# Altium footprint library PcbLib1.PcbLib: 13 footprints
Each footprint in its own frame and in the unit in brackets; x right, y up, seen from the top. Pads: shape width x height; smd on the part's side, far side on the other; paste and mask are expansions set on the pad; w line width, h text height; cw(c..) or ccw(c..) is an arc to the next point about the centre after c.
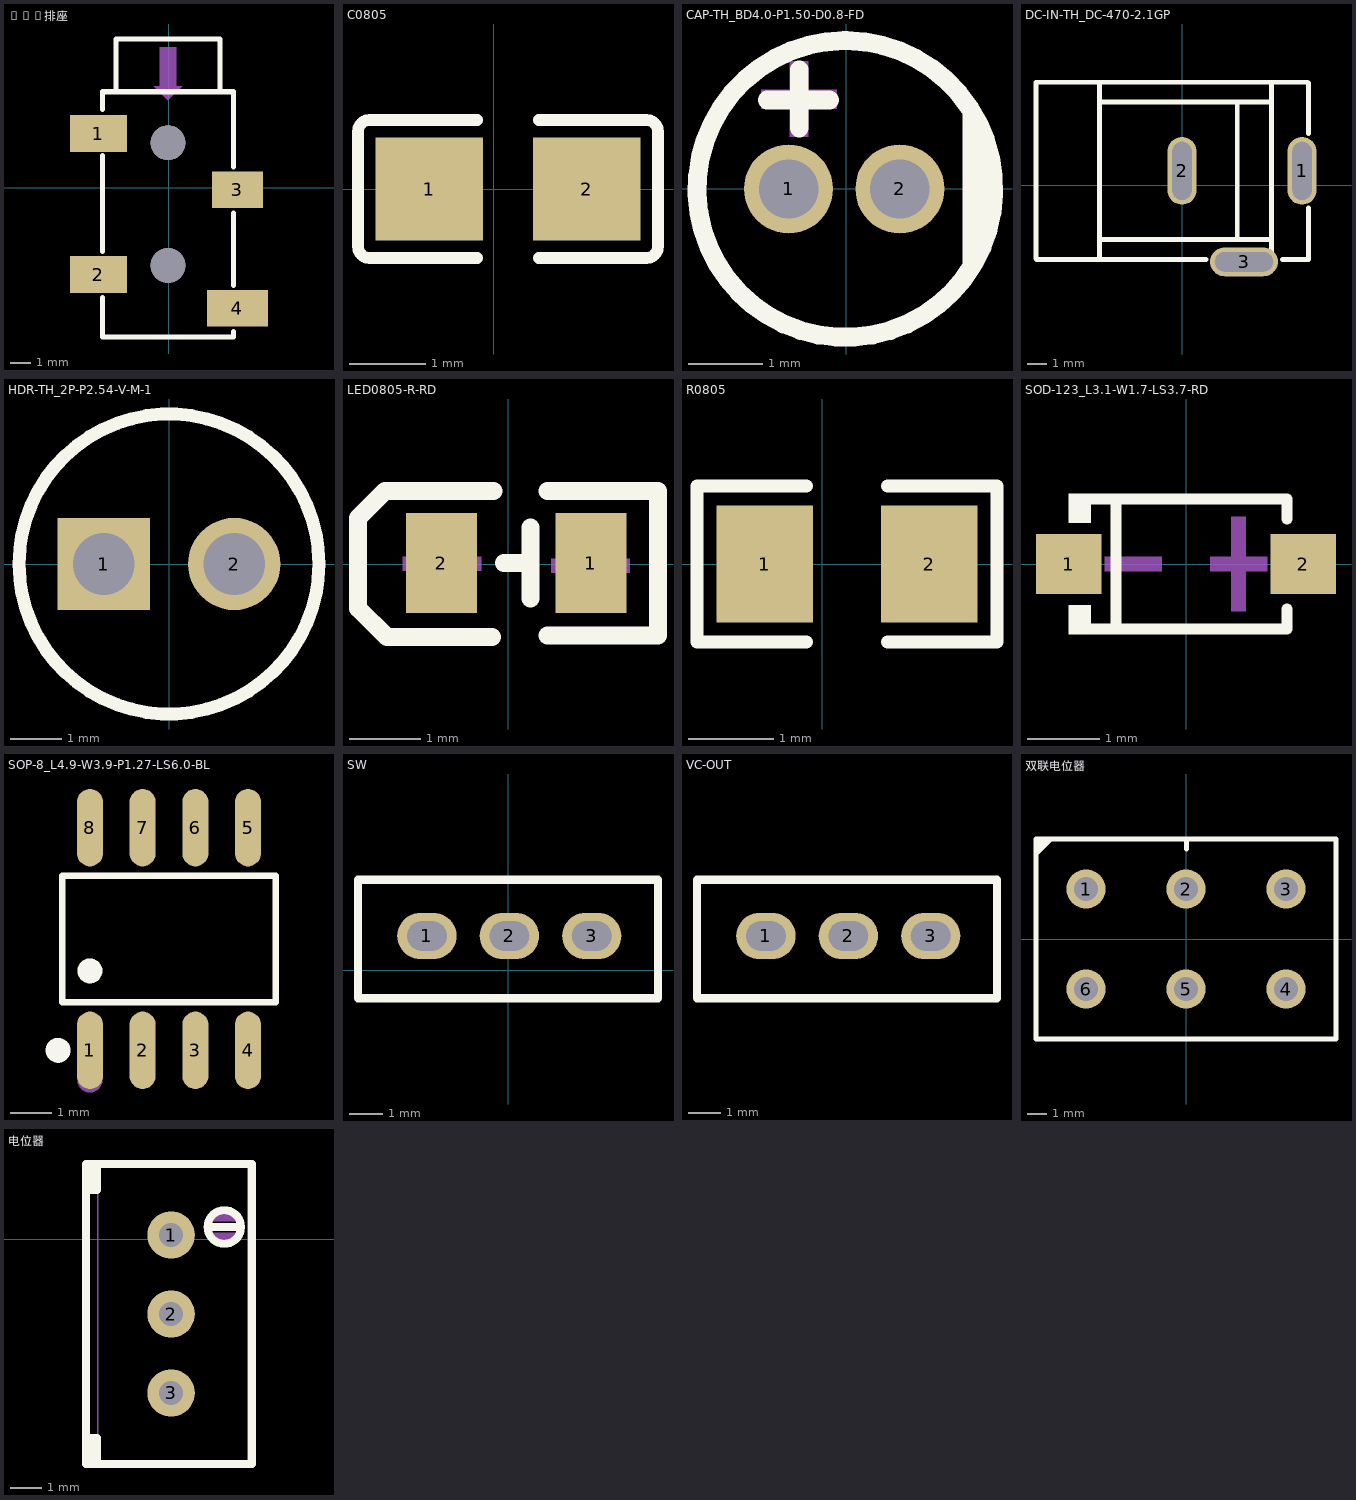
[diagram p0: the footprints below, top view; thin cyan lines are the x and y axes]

## 3.5排座 [mm]
pads (6):
  rect 2.8x1.8 smd: 1(-3.45,2.66) 2(-3.45,-4.24)
  rect 2.5x1.8 smd: 3(3.35,-0.09)
  rect 3x1.8 smd: 4(3.35,-5.89)
  round 1.7 hole 1.7 unplated: ""(-0.05,-3.79) ""(-0.05,2.21)
Top Overlay:
  lines w0.254: -3.25,-5.371 -3.25,-7.29 3.15,-7.29 3.15,-7.021 ; -3.25,-3.109 -3.25,-2.959 -3.25,1.579 ; -3.25,3.841 -3.25,4.71 3.15,4.71 3.15,1.041 ; -2.59,4.71 -2.59,6.742 -2.59,7.29 2.49,7.29 2.49,6.598 ; 2.49,4.71 2.49,6.742 ; 3.15,-4.759 3.15,-1.221
Mechanical 15:
  region: -0.45,6.885 -0.45,4.985 -0.75,4.985 -0.05,4.285 0.65,4.985 0.35,4.985 0.35,6.885

## C0805 [mm]
pads (2):
  rect 1.41x1.35 smd: 1(-0.843,0) 2(1.217,0)
Top Overlay:
  lines w0.152: -0.215,-0.904 -1.625,-0.904 cw(c-1.625,-0.751) -1.777,-0.751 -1.777,0.751 cw(c-1.625,0.751) -1.625,0.904 -0.215,0.904 ; 0.588,-0.904 1.998,-0.904 ccw(c1.998,-0.751) 2.15,-0.751 2.15,0.751 ccw(c1.998,0.751) 1.998,0.904 0.588,0.904
Top Paste:
  region: 0.662,-0.62 0.662,-0.2 1.107,-0.2 1.107,0.25 0.667,0.25 0.662,0.66 0.712,0.71 1.862,0.71 1.912,0.66 1.912,-0.62 1.862,-0.67 0.712,-0.67
  region: -1.488,-0.62 -1.488,0.66 -1.438,0.71 -0.288,0.71 -0.238,0.66 -0.233,0.25 -0.683,0.25 -0.683,-0.2 -0.243,-0.2 -0.238,-0.62 -0.288,-0.67 -1.438,-0.67

## CAP-TH_BD4.0-P1.50-D0.8-FD [mm]
pads (2):
  round 1.2 hole 0.8: 1(-0.775,0.001) 2(0.725,0.001)
Top Overlay:
  region: 1.575,-1.199 1.685,-1.077 1.857,-0.795 1.975,-0.488 2.035,-0.164 2.035,0.165 1.975,0.489 1.857,0.797 1.685,1.078 1.575,1.201
  lines w0.254: -1.063,1.201 -0.225,1.201 ; -0.631,0.82 -0.631,1.607 ; -0.026,2 ccw(c-0.009,0) 0.007,2
Mechanical 15:
  region: -1.143,1.338 -0.762,1.338 -0.127,1.338 -0.127,1.084 -1.143,1.084
  region: -0.762,0.703 -0.762,1.084 -0.762,1.719 -0.508,1.719 -0.508,0.703
  region: 1.626,1.017 1.717,0.926 1.859,0.713 1.957,0.476 2.007,0.225 2.007,0.097 2.007,-0.126 2.007,-0.222 2.007,-0.351 1.957,-0.602 1.859,-0.839 1.717,-1.052 1.626,-1.142

## DC-IN-TH_DC-470-2.1GP [mm]
pads (3):
  oval 1.5x3.5 hole 1 slot 3 at 90 deg: 1(6.183,0.751) 2(-0.017,0.751)
  oval 3.5x1.5 hole 1 slot 3 at 0 deg: 3(3.183,-3.95)
Top Overlay:
  lines w0.254: -4.276,-2.805 4.614,-2.805 ; -4.276,4.307 4.614,4.307 ; 1.211,-3.821 -4.276,-3.821 ; 2.836,-2.805 2.836,4.307 ; 4.614,-3.821 4.614,5.323 ; 5.156,-3.821 6.503,-3.821 6.503,-1.177 ; 6.503,2.678 6.503,5.283 6.463,5.323 -4.276,5.323 ; -4.276,-3.821 -4.276,5.323 ; -4.276,-3.821 -7.524,-3.821 -7.556,-3.789 -7.556,5.323 -4.276,5.323

## HDR-TH_2P-P2.54-V-M-1 [mm]
pads (2):
  rect 1.8x1.8 hole 1.2: 1(-1.27,0)
  round 1.8 hole 1.2: 2(1.27,0)
Top Overlay:
  circle w0.254: c0,0 r2.924

## LED0805-R-RD [mm]
pads (2):
  rect 1x1.4 smd: 1(1.166,0.014) 2(-0.935,0.014)
Top Overlay:
  lines w0.254: -0.229,-1.029 -1.702,-1.029 -2.108,-0.622 -2.108,0.648 -1.727,1.029 -0.203,1.029 ; -0.053,0.014 0.216,0.014 ; 0.316,-0.486 0.316,0.514 ; 0.559,-1.003 2.108,-1.003 2.108,1.029 0.559,1.029
Mechanical 15:
  region: 1.057,-0.542 1.057,0.558 1.257,0.558 1.257,-0.542
  region: 0.61,0.074 1.71,0.074 1.71,-0.126 0.61,-0.126
  region: -0.379,-0.095 -1.479,-0.095 -1.479,0.105 -0.379,0.105

## R0805 [mm]
pads (2):
  rect 1.133x1.377 smd: 1(-0.678,0) 2(1.254,0)
Top Overlay:
  lines w0.152: -0.188,-0.917 -1.473,-0.917 -1.473,0.917 -0.188,0.917 ; 0.764,-0.917 2.049,-0.917 2.049,0.917 0.764,0.917
Top Paste:
  region: -1.412,-0.64 -1.412,0.64 -1.362,0.69 -0.212,0.69 -0.162,0.64 -0.157,0.23 -0.607,0.23 -0.607,-0.22 -0.167,-0.22 -0.162,-0.64 -0.212,-0.69 -1.362,-0.69
  region: 0.738,-0.64 0.738,-0.22 1.183,-0.22 1.183,0.23 0.743,0.23 0.738,0.64 0.788,0.69 1.938,0.69 1.988,0.64 1.988,-0.64 1.938,-0.69 0.788,-0.69

## SOD-123_L3.1-W1.7-LS3.7-RD [mm]
pads (2):
  rect 0.91x0.84 smd: 1(-1.63,0) 2(1.63,0)
Top Overlay:
  region: -1.325,0.977 -1.325,0.572 -1.63,0.572 -1.63,0.977
  region: -1.325,-0.977 -1.325,-0.572 -1.63,-0.572 -1.63,-0.977
  lines w0.152: -1.401,-0.901 1.401,-0.901 1.401,-0.623 ; -1.401,0.901 1.401,0.901 1.401,0.623 ; -0.972,-0.901 -0.972,0.901
Mechanical 15:
  region: -1.127,0.099 -1.127,-0.099 -0.335,-0.099 -0.335,0.099
  region: 1.127,0.099 1.127,-0.099 0.335,-0.099 0.335,0.099
  region: 0.83,0.66 0.83,-0.66 0.632,-0.66 0.632,0.66

## SOP-8_L4.9-W3.9-P1.27-LS6.0-BL [mm]
pads (8):
  oval 0.63x1.865 smd: 1(420.503,-434.048) 2(421.773,-434.048) 3(423.043,-434.048) 4(424.313,-434.048) 5(424.313,-428.683) 6(423.043,-428.683) 7(421.773,-428.683) 8(420.503,-428.683)
Top Overlay:
  circle w0.3: c420.503,-432.135 r0.15
  circle w0.3: c419.735,-434.048 r0.15
  lines w0.152: 419.832,-432.887 419.832,-429.844 424.984,-429.844 424.984,-432.887 419.832,-432.887
Mechanical 15:
  circle w0.3: c420.503,-434.766 r0.15

## SW [mm]
pads (3):
  oval 1.8x1.4 hole 0.9 slot 1.2 at 0 deg: 1(-2.46,1.036) 2(0.04,1.036) 3(2.54,1.036)
Top Overlay:
  lines w0.254: -4.55,-0.856 -4.55,2.744 4.55,2.744 4.55,-0.856 -4.55,-0.856

## VC-OUT [mm]
pads (3):
  oval 1.8x1.4 hole 0.9 slot 1.2 at 0 deg: 1(-1259.379,308.884) 2(-1256.879,308.884) 3(-1254.379,308.884)
Top Overlay:
  lines w0.254: -1261.469,306.992 -1252.369,306.992 -1252.369,310.592 -1261.469,310.592 -1261.469,306.992

## 双联电位器 [mm]
pads (6):
  round 2 hole 1.2: 1(-5.08,2.54) 2(0,2.54) 3(5.08,2.54) 4(5.08,-2.54) 5(0,-2.54) 6(-5.08,-2.54)
Top Overlay:
  region: -6.731,5.08 -7.62,5.08 -7.62,4.191
  lines w0.254: 0.013,4.572 0.013,5.08 ; -7.62,-5.08 -7.62,5.08 7.62,5.08 7.62,-5.08 -7.62,-5.08

## 电位器 [mil]
pads (3):
  round 60 hole 30 paste+0 mask+2: 1(252.64,5) 2(252.64,-95) 3(252.64,-195)
Top Overlay:
  lines w10: 305,15.4 320,15.4 ; 341.25,15 cw(c319.99,15.2) 341.25,15.4 ; 320,15.4 335,15.4 320,15.4 ; 145,-285 145,95 355,95 355,-285 145,-285 ; 151.06,-282 151.06,-252 158.93,-252 158.93,-282 151.06,-282 ; 151.06,62.01 151.06,92.01 158.93,92.01 158.93,62.01 151.06,62.01
Mechanical 6:
  region: 300.09,8.15 301.23,5.11 305.22,-0.01 310.56,-3.71 316.75,-5.65 323.25,-5.65 329.44,-3.71 334.78,-0.01 338.77,5.11 339.91,8.15
  region: 339.91,22.65 338.77,25.69 334.78,30.81 329.44,34.51 323.25,36.45 316.75,36.45 310.56,34.51 305.22,30.81 301.23,25.69 300.09,22.65
Mechanical 15:
  region: 262.48,-195.39 262.48,-193.43 260.98,-189.82 258.21,-187.05 254.6,-185.55 250.68,-185.55 247.06,-187.05 244.29,-189.82 242.8,-193.43 242.8,-195.39 242.8,-197.35 244.29,-200.96 247.06,-203.73 250.68,-205.23 254.6,-205.23 258.21,-203.73 260.98,-200.96 262.48,-197.35 262.48,-195.39
  region: 262.48,-94.6 262.48,-92.64 260.98,-89.03 258.21,-86.26 254.6,-84.76 250.68,-84.76 247.06,-86.26 244.29,-89.03 242.8,-92.64 242.8,-94.6 242.8,-96.56 244.29,-100.17 247.06,-102.94 250.68,-104.44 254.6,-104.44 258.21,-102.94 260.98,-100.17 262.48,-96.56 262.48,-94.6
  region: 262.48,5.4 262.48,7.36 260.98,10.97 258.21,13.74 254.6,15.24 250.68,15.24 247.06,13.74 244.29,10.97 242.8,7.36 242.8,5.4 242.8,3.44 244.29,-0.17 247.06,-2.94 250.68,-4.44 254.6,-4.44 258.21,-2.94 260.98,-0.17 262.48,3.44 262.48,5.4
  region: 162.28,92.6 162.28,93.58 160.9,94.96 158.94,94.96 157.56,93.58 157.56,92.6 157.56,91.62 158.94,90.24 160.9,90.24 162.28,91.62 162.28,92.6
  lines w2: 159.92,-282.59 159.92,92.6 350.08,92.6 350.08,-282.59 159.92,-282.59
